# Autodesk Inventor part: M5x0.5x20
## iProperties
IsCustomPart: 0
Created: 2009-02
Part Number: M5x0.5x20
Material: Steel, Mild
Description: 6각머리 태핑 나사
Document SubType Name: Modeling
Standard: KS B 1003
Designer: SeoGD™
Standards Organization: KS
Language: ko-KR
Size Designation: M 5 x 20
Categories: <MemberInstance><Categories><Category DisplayName="조임쇠" InternalName="e4da775c-781d-43d5-af7c-5136215cf5a6" Mnemonic="FSTN"><Category DisplayName="볼트" InternalN
Density: 1 g/cm^3
Author: SeoGD™
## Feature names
1. Fillet2
